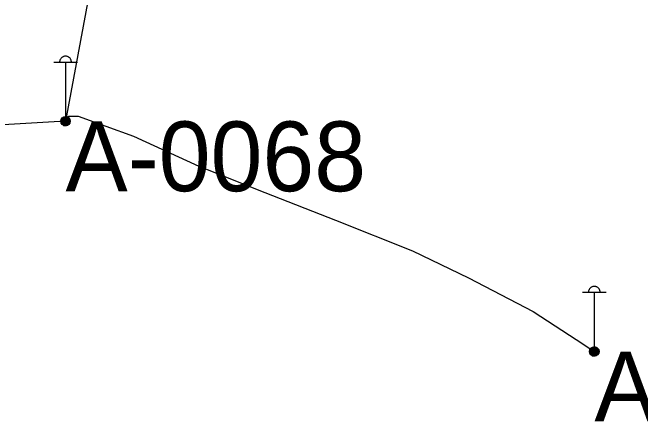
# Model space of a CAD drawing. Extents: x -729889 to -691139, y -995431 to -974354.
# Drawn here: x -725634.94 to -725607.91, y -978174.49 to -978156.87 of the extents above; entities that cross this region are included whole.
import ezdxf

# ---------------------------------------------------------------- set-up
doc = ezdxf.new("R2010")
doc.units = 0
for name, color, linetype in [('Atributy', 7, 'Continuous'), ('Kabelové vedení VO', 7, 'Continuous'), ('Světelný bod na stožáru sadovém', 7, 'Continuous')]:
    doc.layers.add(name, color=color, linetype=linetype)

# ---------------------------------------------------------------- blocks, each defined once
blk = doc.blocks.new('6.571')
at = {"layer": 'Světelný bod na stožáru sadovém'}
for p, q in [((-0.508, 2.538), (0.508, 2.538)), ((0, 2.538), (0, 0.203))]:
    blk.add_line(p, q, dxfattribs=at)
for points in [[(0.254, 2.538), (0.254, 2.558), (0.249, 2.584), (0.244, 2.604), (0.239, 2.624), (0.228, 2.645), (0.218, 2.665), (0.208, 2.685), (0.193, 2.701), (0.178, 2.716), (0.162, 2.731), (0.147, 2.746), (0.127, 2.756), (0.107, 2.766), (0.086, 2.777), (0.066, 2.782), (0.046, 2.787), (0.02, 2.792), (0, 2.792), (-0.02, 2.792), (-0.046, 2.787), (-0.066, 2.782), (-0.086, 2.777), (-0.107, 2.766), (-0.127, 2.756), (-0.147, 2.746), (-0.162, 2.731), (-0.178, 2.716), (-0.193, 2.701), (-0.208, 2.685), (-0.218, 2.665), (-0.228, 2.645), (-0.239, 2.624), (-0.244, 2.604), (-0.249, 2.584), (-0.254, 2.558), (-0.254, 2.538)], [(-0.203, 0), (-0.173, -0.102), (-0.076, -0.183), (0.041, -0.188), (0.132, -0.142), (0.188, -0.046), (0.178, 0.071), (0.117, 0.152), (0.02, 0.193), (-0.091, 0.168), (-0.168, 0.086), (-0.183, -0.005), (-0.147, -0.102), (-0.056, -0.168), (0.041, -0.168), (0.122, -0.122), (0.173, -0.025), (0.157, 0.076), (0.102, 0.142), (0.005, 0.173), (-0.091, 0.142), (-0.147, 0.071), (-0.162, -0.01), (-0.122, -0.102), (-0.041, -0.152), (0.041, -0.147), (0.117, -0.102), (0.152, -0.01), (0.137, 0.071), (0.081, 0.132), (-0.005, 0.152), (-0.086, 0.122), (-0.132, 0.061), (-0.142, -0.02), (-0.096, -0.096), (-0.03, -0.132), (0.041, -0.127), (0.107, -0.076), (0.132, 0), (0.117, 0.066), (0.061, 0.117), (-0.015, 0.132), (-0.081, 0.102), (-0.117, 0.046), (-0.122, -0.025), (-0.081, -0.086), (-0.02, -0.112), (0.046, -0.107), (0.096, -0.056), (0.112, 0.005), (0.096, 0.061), (0.046, 0.107), (-0.02, 0.112), (-0.071, 0.086), (-0.102, 0.036), (-0.096, -0.03), (-0.061, -0.076), (-0.015, -0.096), (0.046, -0.081), (0.086, -0.041), (0.096, 0.005), (0.076, 0.056), (0.03, 0.091), (-0.02, 0.091), (-0.061, 0.066), (-0.081, 0.02), (-0.076, -0.03), (-0.051, -0.061), (-0.005, -0.076), (0.041, -0.061), (0.066, -0.03), (0.071, 0.01), (0.056, 0.051), (0.02, 0.071), (-0.015, 0.071), (-0.051, 0.051), (-0.066, 0.015), (-0.056, -0.025), (-0.036, -0.046), (0, -0.056), (0.036, -0.041), (0.051, -0.02), (0.056, 0.01), (0.041, 0.041), (0.01, 0.051), (-0.015, 0.051), (-0.036, 0.036), (-0.046, 0.005), (-0.041, -0.015), (-0.02, -0.03), (0.005, -0.036), (0.025, -0.025), (0.036, -0.01), (0.036, 0.01), (0.02, 0.025), (0.005, 0.036), (-0.01, 0.03), (-0.02, 0.02), (-0.025, 0.005), (-0.02, -0.01), (-0.01, -0.015)], [(-0.01, -0.015), (0.005, -0.015), (0.01, -0.01), (0.015, 0), (0.015, 0.01), (0.01, 0.015), (0, 0.015), (-0.005, 0.01), (-0.005, 0.005), (-0.005, 0.005)]]:
    blk.add_lwpolyline(points, dxfattribs=at)
blk.add_circle((0, 0), 0.203, dxfattribs=at)

msp = doc.modelspace()

# ---------------------------------------------------------------- linework, layer by layer
at = {"layer": 'Kabelové vedení VO'}
for p, q in [((-725630.81, -978151.57), (-725632.66, -978161.54)), ((-725632.66, -978161.54), (-725661.68, -978163.22))]:
    msp.add_line(p, q, dxfattribs=at)
msp.add_lwpolyline([(-725632.66, -978161.54), (-725632.515, -978161.324), (-725632.118, -978161.324), (-725629.737, -978162.184), (-725626.926, -978163.474), (-725624.082, -978164.599), (-725621.039, -978165.789), (-725617.732, -978167.112), (-725615.317, -978168.27), (-725612.539, -978169.725), (-725610.356, -978171.147), (-725609.9, -978171.44)], dxfattribs=at)

# ---------------------------------------------------------------- block references
at = {"layer": 'Světelný bod na stožáru sadovém', "xscale": 1.0016949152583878, "yscale": 1.0016949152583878}
for p in [(-725632.66, -978161.54), (-725609.9, -978171.44)]:
    msp.add_blockref('6.571', p, dxfattribs=at)

# ---------------------------------------------------------------- texts
at = {"layer": 'Atributy'}
for s, p in [('A-0068', (-725632.66, -978164.551)), ('A-0069', (-725609.9, -978174.451))]:
    msp.add_text(s, height=3, dxfattribs=at).set_placement(p)

doc.saveas('drawing.dxf')
